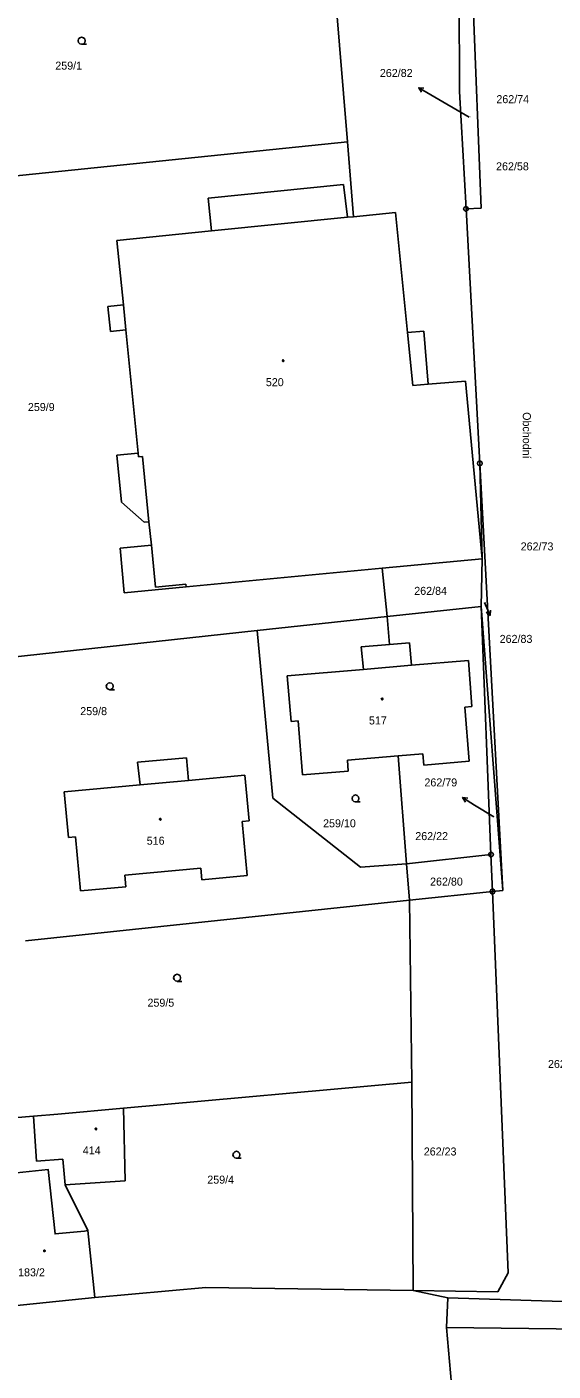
# Model space of a CAD drawing. Extents: x -757994 to -755874, y -1047691 to -1046119.
# Drawn here: x -757420.1 to -757364.3, y -1047392.5 to -1047249.7 of the extents above; entities that cross this region are included whole.
import ezdxf

# ---------------------------------------------------------------- set-up
doc = ezdxf.new("R2010")
doc.units = 0
doc.layers.add('katastrální mapa', color=7, linetype='Continuous')

msp = doc.modelspace()

# ---------------------------------------------------------------- linework, layer by layer
at = {"layer": 'katastrální mapa'}
for p, q in [((-757373.9, -1047219.06), (-757371.91, -1047269)), ((-757386.11, -1047261.95), (-757387.53, -1047244.64)), ((-757374.19, -1047256.6), (-757374.24, -1047246.51)), ((-757378.53, -1047256.2), (-757377.24, -1047256.96)), ((-757373.18, -1047259.34), (-757377.24, -1047256.96)), ((-757374.19, -1047256.6), (-757373.51, -1047269.07)), ((-757426.34, -1047266.07), (-757386.11, -1047261.95)), ((-757386.11, -1047261.95), (-757385.46, -1047269.9)), ((-757400.88, -1047267.93), (-757386.52, -1047266.49)), ((-757386.52, -1047266.49), (-757386.09, -1047269.96)), ((-757400.53, -1047271.41), (-757400.88, -1047267.93)), ((-757373.57, -1047269.07), (-757373.45, -1047269.07)), ((-757371.91, -1047269), (-757373.51, -1047269.07)), ((-757373.51, -1047269.07), (-757372.05, -1047296.09)), ((-757400.53, -1047271.41), (-757386.09, -1047269.96)), ((-757386.09, -1047269.96), (-757385.46, -1047269.9)), ((-757385.46, -1047269.9), (-757380.99, -1047269.45)), ((-757380.99, -1047269.45), (-757379.71, -1047282.2)), ((-757410.58, -1047272.42), (-757400.53, -1047271.41)), ((-757409.9, -1047279.26), (-757410.58, -1047272.42)), ((-757411.54, -1047279.42), (-757409.9, -1047279.26)), ((-757411.27, -1047282.08), (-757411.54, -1047279.42)), ((-757409.9, -1047279.26), (-757409.63, -1047281.91)), ((-757409.63, -1047281.91), (-757411.27, -1047282.08)), ((-757408.32, -1047295.01), (-757409.63, -1047281.91)), ((-757379.71, -1047282.2), (-757378.01, -1047282.06)), ((-757379.71, -1047282.2), (-757379.15, -1047287.82)), ((-757378.01, -1047282.06), (-757377.55, -1047287.69)), ((-757377.55, -1047287.69), (-757373.56, -1047287.36)), ((-757373.56, -1047287.36), (-757371.8, -1047306.23)), ((-757379.15, -1047287.82), (-757377.55, -1047287.69)), ((-757410.58, -1047295.23), (-757408.32, -1047295.01)), ((-757410.09, -1047300.19), (-757410.58, -1047295.23)), ((-757408.28, -1047295.39), (-757408.32, -1047295.01)), ((-757407.88, -1047295.35), (-757408.28, -1047295.39)), ((-757407.19, -1047302.28), (-757407.88, -1047295.35)), ((-757372.11, -1047296.09), (-757371.99, -1047296.09)), ((-757371.8, -1047306.23), (-757372.05, -1047296.09)), ((-757372.05, -1047296.09), (-757369.59, -1047341.43)), ((-757407.68, -1047302.33), (-757410.09, -1047300.19)), ((-757407.19, -1047302.28), (-757407.68, -1047302.33)), ((-757407.19, -1047302.28), (-757406.93, -1047304.79)), ((-757406.93, -1047304.79), (-757410.25, -1047305.1)), ((-757410.25, -1047305.1), (-757409.8, -1047309.83)), ((-757406.93, -1047304.79), (-757406.49, -1047309.23)), ((-757382.41, -1047307.23), (-757403.23, -1047309.21)), ((-757371.8, -1047306.23), (-757382.41, -1047307.23)), ((-757382.41, -1047307.23), (-757381.87, -1047312.35)), ((-757371.92, -1047311.28), (-757371.8, -1047306.23)), ((-757406.49, -1047309.23), (-757403.26, -1047308.91)), ((-757403.26, -1047308.91), (-757403.23, -1047309.21)), ((-757409.8, -1047309.83), (-757403.23, -1047309.21)), ((-757381.87, -1047312.35), (-757371.92, -1047311.28)), ((-757371.92, -1047311.28), (-757370.86, -1047337.63)), ((-757371.92, -1047311.28), (-757369.59, -1047341.43)), ((-757370.96, -1047312.23), (-757371.56, -1047310.86)), ((-757395.69, -1047313.85), (-757381.87, -1047312.35)), ((-757381.64, -1047315.31), (-757381.87, -1047312.35)), ((-757422.35, -1047316.74), (-757395.69, -1047313.85)), ((-757395.69, -1047313.85), (-757394.02, -1047331.63)), ((-757384.64, -1047315.56), (-757381.64, -1047315.31)), ((-757384.41, -1047317.96), (-757384.64, -1047315.56)), ((-757381.64, -1047315.31), (-757379.51, -1047315.13)), ((-757379.51, -1047315.13), (-757379.31, -1047317.53)), ((-757384.41, -1047317.96), (-757379.31, -1047317.53)), ((-757379.31, -1047317.53), (-757373.26, -1047317.03)), ((-757373.26, -1047317.03), (-757372.9, -1047321.91)), ((-757392.5, -1047318.64), (-757384.41, -1047317.96)), ((-757392.08, -1047323.5), (-757392.5, -1047318.64)), ((-757372.9, -1047321.91), (-757373.63, -1047321.98)), ((-757373.63, -1047321.98), (-757373.19, -1047327.72)), ((-757391.35, -1047323.44), (-757392.08, -1047323.5)), ((-757390.86, -1047329.17), (-757391.35, -1047323.44)), ((-757408.39, -1047327.8), (-757403.2, -1047327.36)), ((-757403.2, -1047327.36), (-757402.98, -1047329.76)), ((-757380.72, -1047327.14), (-757386.1, -1047327.59)), ((-757386.1, -1047327.59), (-757386.03, -1047328.77)), ((-757378.09, -1047326.92), (-757380.72, -1047327.14)), ((-757379.84, -1047338.6), (-757380.72, -1047327.14)), ((-757377.98, -1047328.13), (-757378.09, -1047326.92)), ((-757408.1, -1047330.22), (-757408.39, -1047327.8)), ((-757386.03, -1047328.77), (-757390.86, -1047329.17)), ((-757373.19, -1047327.72), (-757377.98, -1047328.13)), ((-757416.17, -1047330.96), (-757408.1, -1047330.22)), ((-757408.1, -1047330.22), (-757402.98, -1047329.76)), ((-757402.98, -1047329.76), (-757396.99, -1047329.2)), ((-757396.99, -1047329.2), (-757396.53, -1047334.04)), ((-757415.73, -1047335.83), (-757416.17, -1047330.96)), ((-757394.02, -1047331.63), (-757384.73, -1047338.98)), ((-757373.88, -1047331.58), (-757372.6, -1047332.37)), ((-757370.57, -1047333.62), (-757372.6, -1047332.37)), ((-757396.53, -1047334.04), (-757397.29, -1047334.12)), ((-757397.29, -1047334.12), (-757396.75, -1047339.85)), ((-757414.99, -1047335.76), (-757415.73, -1047335.83)), ((-757414.45, -1047341.49), (-757414.99, -1047335.76)), ((-757384.73, -1047338.98), (-757379.84, -1047338.6)), ((-757379.84, -1047338.6), (-757370.86, -1047337.63)), ((-757379.52, -1047342.48), (-757379.84, -1047338.6)), ((-757370.92, -1047337.63), (-757370.8, -1047337.63)), ((-757370.86, -1047337.63), (-757370.7, -1047341.55)), ((-757401.69, -1047339.08), (-757409.74, -1047339.83)), ((-757409.74, -1047339.83), (-757409.64, -1047341.07)), ((-757401.58, -1047340.32), (-757401.69, -1047339.08)), ((-757396.75, -1047339.85), (-757401.58, -1047340.32)), ((-757409.64, -1047341.07), (-757414.45, -1047341.49)), ((-757370.7, -1047341.55), (-757379.52, -1047342.48)), ((-757370.76, -1047341.55), (-757370.64, -1047341.55)), ((-757369.59, -1047341.43), (-757370.7, -1047341.55)), ((-757370.7, -1047341.55), (-757369.03, -1047382.05)), ((-757379.52, -1047342.48), (-757420.31, -1047346.77)), ((-757379.52, -1047342.48), (-757379.27, -1047361.78)), ((-757379.27, -1047361.78), (-757409.9, -1047364.57)), ((-757379.27, -1047361.78), (-757379.12, -1047383.93)), ((-757409.9, -1047364.57), (-757416.87, -1047365.2)), ((-757409.9, -1047364.57), (-757409.72, -1047372.26)), ((-757419.46, -1047365.42), (-757423.24, -1047365.74)), ((-757416.87, -1047365.2), (-757419.46, -1047365.42)), ((-757419.12, -1047370.18), (-757419.46, -1047365.42)), ((-757416.33, -1047369.97), (-757419.12, -1047370.18)), ((-757416.09, -1047372.68), (-757416.33, -1047369.97)), ((-757409.72, -1047372.26), (-757416.09, -1047372.68)), ((-757416.09, -1047372.68), (-757413.68, -1047377.56)), ((-757413.68, -1047377.56), (-757414.03, -1047377.6)), ((-757413.68, -1047377.56), (-757412.92, -1047384.66)), ((-757369.03, -1047382.05), (-757370.14, -1047384.04)), ((-757423.31, -1047385.71), (-757412.92, -1047384.66)), ((-757412.92, -1047384.66), (-757401.15, -1047383.58)), ((-757379.12, -1047383.93), (-757401.15, -1047383.58)), ((-757379.12, -1047383.93), (-757375.44, -1047384.68)), ((-757370.14, -1047384.04), (-757379.12, -1047383.93)), ((-757375.44, -1047384.68), (-757375.59, -1047387.84)), ((-757254.95, -1047388.51), (-757375.44, -1047384.68)), ((-757375.59, -1047387.84), (-757375.06, -1047393.86)), ((-757181.2, -1047390.32), (-757375.59, -1047387.84))]:
    msp.add_line(p, q, dxfattribs=at)
for points in [[(-757414.32, -1047251.58), (-757414.51, -1047251.53), (-757414.65, -1047251.4), (-757414.7, -1047251.21), (-757414.65, -1047251.02), (-757414.51, -1047250.89), (-757414.33, -1047250.84), (-757414.14, -1047250.89), (-757414, -1047251.02), (-757413.96, -1047251.22), (-757414, -1047251.41), (-757414.14, -1047251.54), (-757414.33, -1047251.59), (-757413.83, -1047251.59)], [(-757378.23, -1047256.67), (-757378.53, -1047256.2), (-757377.98, -1047256.24)], [(-757370.93, -1047311.68), (-757370.96, -1047312.23), (-757371.39, -1047311.88)], [(-757411.34, -1047320.12), (-757411.53, -1047320.07), (-757411.67, -1047319.94), (-757411.72, -1047319.75), (-757411.67, -1047319.57), (-757411.53, -1047319.43), (-757411.35, -1047319.38), (-757411.16, -1047319.43), (-757411.02, -1047319.57), (-757410.98, -1047319.76), (-757411.02, -1047319.95), (-757411.16, -1047320.08), (-757411.35, -1047320.13), (-757410.85, -1047320.13)], [(-757385.25, -1047332.03), (-757385.44, -1047331.98), (-757385.58, -1047331.85), (-757385.62, -1047331.66), (-757385.58, -1047331.48), (-757385.44, -1047331.34), (-757385.26, -1047331.29), (-757385.07, -1047331.34), (-757384.94, -1047331.48), (-757384.89, -1047331.67), (-757384.94, -1047331.86), (-757385.07, -1047331.99), (-757385.26, -1047332.04), (-757384.76, -1047332.04)], [(-757373.58, -1047332.06), (-757373.88, -1047331.58), (-757373.32, -1047331.63)], [(-757404.18, -1047351.08), (-757404.37, -1047351.03), (-757404.51, -1047350.9), (-757404.56, -1047350.71), (-757404.51, -1047350.52), (-757404.37, -1047350.39), (-757404.19, -1047350.34), (-757404, -1047350.39), (-757403.86, -1047350.52), (-757403.82, -1047350.72), (-757403.86, -1047350.91), (-757404, -1047351.04), (-757404.19, -1047351.09), (-757403.69, -1047351.09)], [(-757397.88, -1047369.87), (-757398.07, -1047369.82), (-757398.21, -1047369.69), (-757398.26, -1047369.5), (-757398.21, -1047369.32), (-757398.07, -1047369.18), (-757397.89, -1047369.13), (-757397.7, -1047369.18), (-757397.57, -1047369.32), (-757397.52, -1047369.51), (-757397.57, -1047369.7), (-757397.7, -1047369.83), (-757397.89, -1047369.88), (-757397.39, -1047369.88)], [(-757414.03, -1047377.6), (-757417.16, -1047377.91), (-757417.9, -1047371.05), (-757423.98, -1047371.71), (-757423.36, -1047377.49), (-757425.89, -1047377.78), (-757425.36, -1047382.2), (-757424.06, -1047382.04), (-757423.6, -1047385.73)]]:
    msp.add_lwpolyline(points, dxfattribs=at)
for points in [[(-757373.44, -1047268.83), (-757373.31, -1047268.92), (-757373.26, -1047269.07), (-757373.31, -1047269.21), (-757373.44, -1047269.3), (-757373.59, -1047269.3), (-757373.72, -1047269.21), (-757373.77, -1047269.07), (-757373.72, -1047268.92), (-757373.59, -1047268.83)], [(-757392.94, -1047285.11), (-757392.89, -1047285.12), (-757392.86, -1047285.16), (-757392.85, -1047285.19), (-757392.86, -1047285.23), (-757392.91, -1047285.27), (-757392.94, -1047285.27), (-757392.98, -1047285.26), (-757393.01, -1047285.23), (-757393.02, -1047285.19), (-757393.01, -1047285.15), (-757392.97, -1047285.11)], [(-757371.98, -1047295.85), (-757371.85, -1047295.94), (-757371.8, -1047296.09), (-757371.85, -1047296.23), (-757371.98, -1047296.32), (-757372.13, -1047296.32), (-757372.26, -1047296.23), (-757372.31, -1047296.09), (-757372.26, -1047295.94), (-757372.13, -1047295.85)], [(-757382.42, -1047321.02), (-757382.37, -1047321.03), (-757382.35, -1047321.08), (-757382.34, -1047321.11), (-757382.35, -1047321.16), (-757382.39, -1047321.19), (-757382.42, -1047321.2), (-757382.47, -1047321.18), (-757382.5, -1047321.15), (-757382.51, -1047321.11), (-757382.5, -1047321.07), (-757382.46, -1047321.03)], [(-757405.98, -1047333.79), (-757405.93, -1047333.8), (-757405.91, -1047333.85), (-757405.9, -1047333.88), (-757405.91, -1047333.93), (-757405.95, -1047333.96), (-757405.98, -1047333.97), (-757406.02, -1047333.95), (-757406.05, -1047333.92), (-757406.07, -1047333.88), (-757406.05, -1047333.84), (-757406.01, -1047333.8)], [(-757370.78, -1047337.39), (-757370.66, -1047337.48), (-757370.61, -1047337.62), (-757370.66, -1047337.77), (-757370.78, -1047337.86), (-757370.94, -1047337.86), (-757371.07, -1047337.77), (-757371.11, -1047337.62), (-757371.07, -1047337.48), (-757370.94, -1047337.39)], [(-757370.62, -1047341.31), (-757370.5, -1047341.4), (-757370.45, -1047341.55), (-757370.5, -1047341.69), (-757370.62, -1047341.78), (-757370.78, -1047341.78), (-757370.91, -1047341.69), (-757370.96, -1047341.55), (-757370.91, -1047341.4), (-757370.78, -1047341.31)], [(-757412.81, -1047366.68), (-757412.76, -1047366.69), (-757412.74, -1047366.73), (-757412.73, -1047366.76), (-757412.74, -1047366.8), (-757412.78, -1047366.84), (-757412.81, -1047366.85), (-757412.85, -1047366.83), (-757412.89, -1047366.8), (-757412.9, -1047366.76), (-757412.89, -1047366.72), (-757412.85, -1047366.68)], [(-757418.29, -1047379.62), (-757418.24, -1047379.64), (-757418.22, -1047379.68), (-757418.21, -1047379.71), (-757418.22, -1047379.75), (-757418.26, -1047379.79), (-757418.29, -1047379.79), (-757418.34, -1047379.78), (-757418.36, -1047379.75), (-757418.38, -1047379.71), (-757418.36, -1047379.67), (-757418.33, -1047379.63)]]:
    msp.add_lwpolyline(points, close=True, dxfattribs=at)

# ---------------------------------------------------------------- texts
for s, height, p in [('259/1', 0.85, (-757417.13, -1047254.28)), ('262/82', 0.85, (-757382.66, -1047255.06)), ('262/74', 0.85, (-757370.29, -1047257.84)), ('262/82', 0.05, (-757373.17, -1047259.34)), ('262/58', 0.85, (-757370.32, -1047264.97)), ('520', 0.85, (-757394.77, -1047287.89)), ('259/9', 0.85, (-757420.04, -1047290.53)), ('262/73', 0.85, (-757367.71, -1047305.33)), ('262/84', 0.85, (-757379.01, -1047310.05)), ('262/83', 0.05, (-757371.55, -1047310.86)), ('262/83', 0.85, (-757369.94, -1047315.15)), ('259/8', 0.85, (-757414.48, -1047322.82)), ('517', 0.85, (-757383.82, -1047323.81)), ('262/79', 0.85, (-757377.93, -1047330.39)), ('259/10', 0.85, (-757388.69, -1047334.73)), ('262/79', 0.05, (-757370.69, -1047333.62)), ('516', 0.85, (-757407.42, -1047336.58)), ('262/22', 0.85, (-757378.9, -1047336.09)), ('262/80', 0.85, (-757377.33, -1047340.92)), ('259/5', 0.85, (-757407.34, -1047353.78)), ('262/67', 0.85, (-757364.81, -1047360.29)), ('414', 0.85, (-757414.21, -1047369.46)), ('262/23', 0.85, (-757378, -1047369.58)), ('259/4', 0.85, (-757400.99, -1047372.57)), ('183/2', 0.85, (-757421.08, -1047382.41))]:
    msp.add_text(s, height=height, dxfattribs=at).set_placement(p)
msp.add_text('Obchodní', height=0.85, rotation=269.9777, dxfattribs=at).set_placement((-757367.48, -1047290.65))

doc.saveas('drawing.dxf')
